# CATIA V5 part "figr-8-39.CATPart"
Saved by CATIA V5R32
Part number: Part2
Bounding box of the stored display mesh (mm): x -50 to 50, y -50 to 50, z 0 to 40
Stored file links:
  D:\PROJECTS\Project 2022\CATIA V5 6R 2022\Resources\Part Files\c08_catia_v5_6r2022_prt\figr-8-39.CATPart
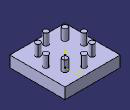
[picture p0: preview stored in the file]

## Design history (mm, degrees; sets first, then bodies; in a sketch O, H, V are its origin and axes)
Body1 (main body)
  Sketch1 on xy-plane, origin (0, 0, 0), H (1, 0, 0), V (0, 1, 0)
    line L1 (-50, 50) -> (50, 50)
    line L2 (50, 50) -> (50, -50)
    line L3 (50, -50) -> (-50, -50)
    line L4 (-50, -50) -> (-50, 50)
    axis line L5 (50, -50) -> (-50, 50)
    length L2 = 100
    length L3 = 100
    horizontal: L1 H, L3 H
    vertical: L2 V, L4 V
    midpoint: O L5
  Pad1: profile Sketch1, direction (0, 0, 1), length 20
  Sketch2 on face of Pad1, origin (0, 0, 20), H (1, 0, 0), V (0, 1, 0)
    circle A1 centre (0, -34.6458) radius 4.7511
    point P1 (0, -34.6458)
    coincidence: P1 V
  Pad2: profile Sketch2, direction (0, 0, 1), length 20
  CircPattern1: of Pad2, instances 8, angular step 45, axis from end face of Pad1
  Sketch3 on yz-plane, origin (0, 0, 0), H (0, 1, 0), V (0, 0, 1)
    line L1 (0, 0) -> (0, 20.0386)
    vertical: L1 V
